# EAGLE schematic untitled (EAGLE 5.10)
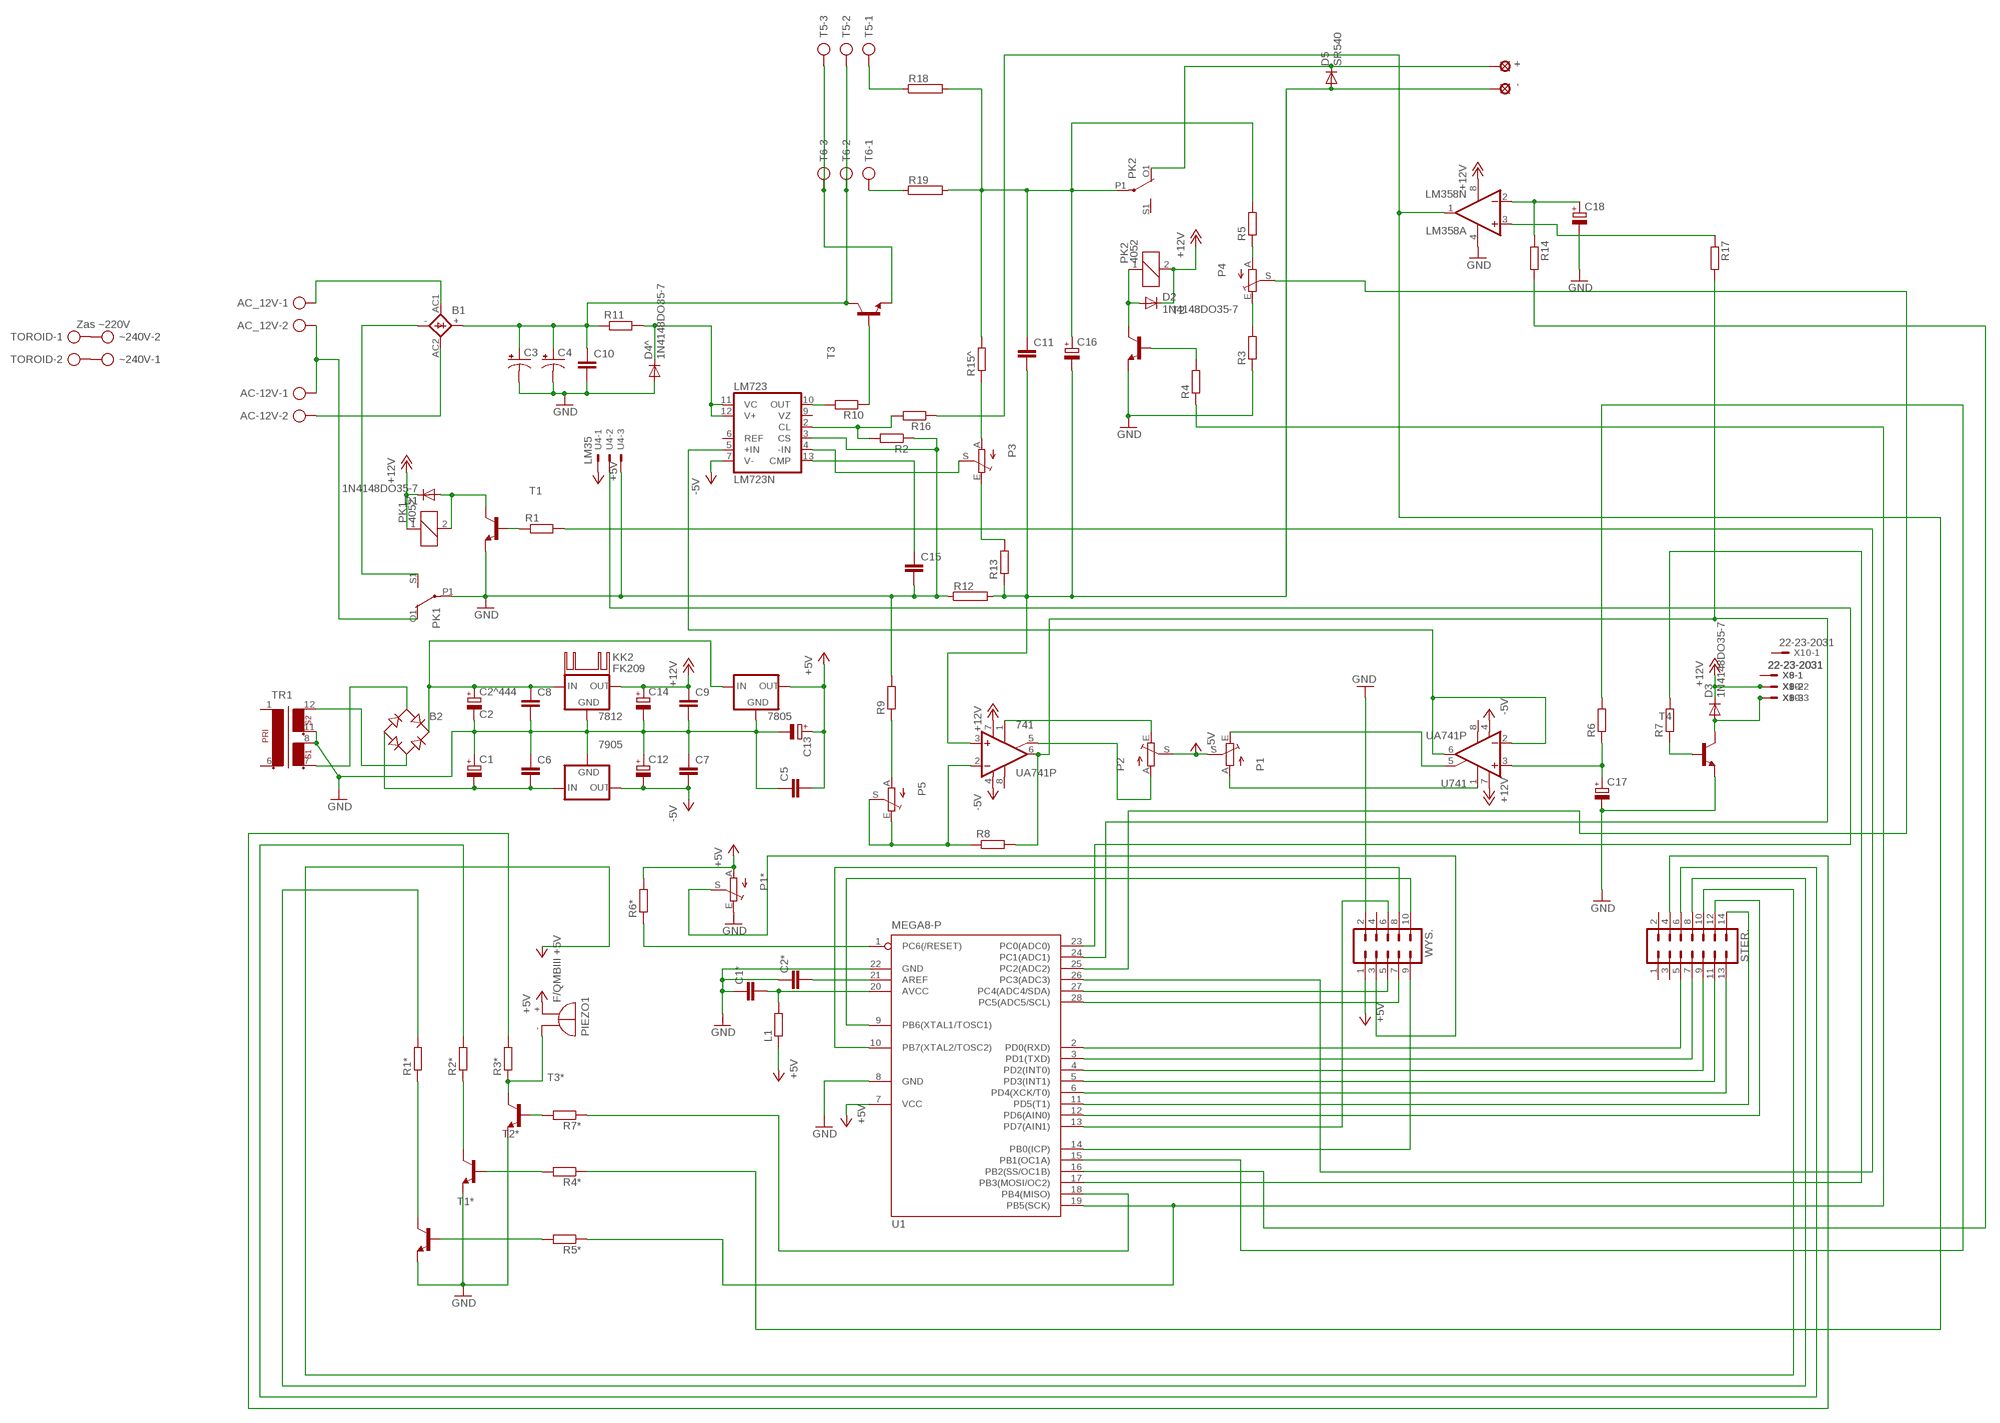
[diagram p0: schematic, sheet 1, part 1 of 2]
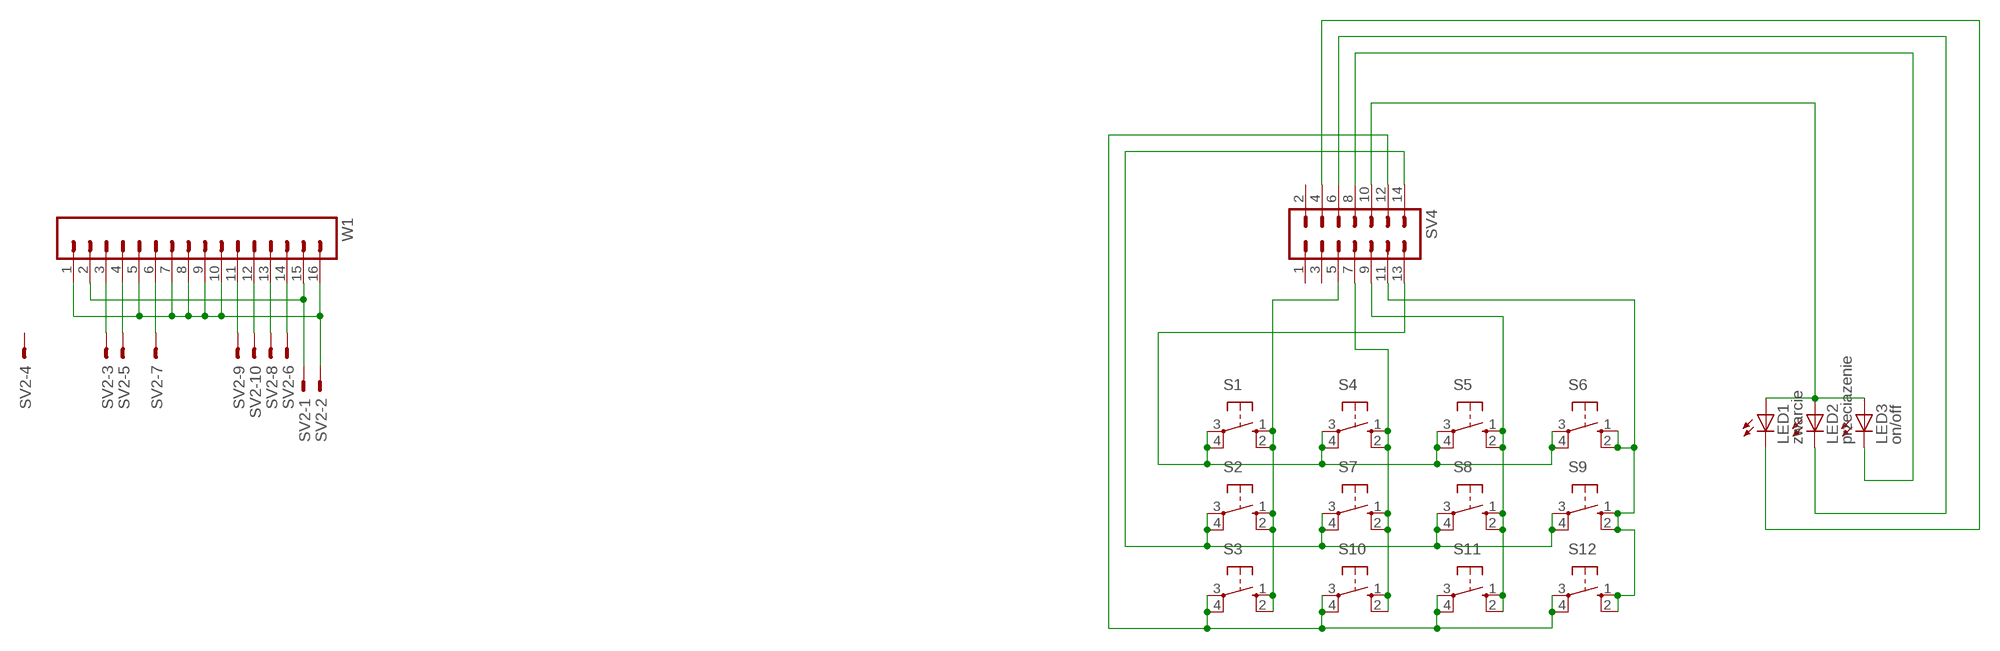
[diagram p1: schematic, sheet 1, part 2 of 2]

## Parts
741  UA741P  [DIL08]
7805  78XXS  [78XXS]
7812  78XXS  [78XXS]
7905  79XXS  [79XXS]
+  LSP10  [LSP10]
-  LSP10  [LSP10]
AC-12V  AK500/2  [AK500/2]
AC_12V  AK500/2  [AK500/2]
B1  FBM  [FBM]
B2  RB1A  [RB1A]
C1  CPOL-EUE3.5-10  [E3,5-10]
C1*  C-EU050-030X075  [C050-030X075]
C2*  C-EU050-030X075  [C050-030X075]
C2^444  C2  CPOL-EUE3.5-10  [E3,5-10]
C3  CPOL-USE7.5-18  [E7,5-18]
C4  CPOL-USE7.5-18  [E7,5-18]
C5  C-EU050-030X075  [C050-030X075]
C6  C-EU050-030X075  [C050-030X075]
C7  C-EU050-030X075  [C050-030X075]
C8  C-EU050-030X075  [C050-030X075]
C9  C-EU050-030X075  [C050-030X075]
C10  C-EU050-030X075  [C050-030X075]
C11  C-EU050-030X075  [C050-030X075]
C12  CPOL-EUE3.5-8  [E3,5-8]
C13  CPOL-EUE3.5-8  [E3,5-8]
C14  CPOL-EUE3.5-8  [E3,5-8]
C15  C-EU050-055X075  [C050-055X075]
C16  CPOL-EUE2.5-6  [E2,5-6]
C17  CPOL-EUE2.5-6  [E2,5-6]
C18  CPOL-EUE2.5-6  [E2,5-6]
D1  1N4148DO35-7  [DO35-7]
D2  1N4148DO35-7  [DO35-7]
D3  1N4148DO35-7  [DO35-7]
D4^  1N4148DO35-7  [DO35-7]
D5  SR540  BYT08P  [TO220ACS]
KK2  FK209  [FK209]
L1  R-EU_0204/7  [0204/7]
LED1  zwarcie  LEDSQR2X5  [LED2X5]
LED2  przeciazenie  LEDSQR2X5  [LED2X5]
LED3  on/off  LEDSQR2X5  [LED2X5]
LM358  LM358N  [DIL08]
LM723  LM723N  [DIL14]
P1  TRIM_EU-SP19L  [SP19L]
P1*  TRIM_EU-CA6V  [CA6V]
P2  TRIM_EU-SP19L  [SP19L]
P3  TRIM_EU-SP19L  [SP19L]
P4  TRIM_EU-SP19L  [SP19L]
P5  TRIM_EU-SP19L  [SP19L]
PIEZO1  F/QMBIII  [F/QMBIII]
PK1  4052  [F4052]
PK2  4052  [F4052]
R1  R-EU_0204/7  [0204/7]
R1*  R-EU_0204/7  [0204/7]
R2  R-EU_0204/7  [0204/7]
R2*  R-EU_0204/7  [0204/7]
R3  R-EU_0204/7  [0204/7]
R3*  R-EU_0204/7  [0204/7]
R4  R-EU_0204/7  [0204/7]
R4*  R-EU_0204/7  [0204/7]
R5  R-EU_0204/7  [0204/7]
R5*  R-EU_0204/7  [0204/7]
R6  R-EU_0204/7  [0204/7]
R6*  R-EU_0204/7  [0204/7]
R7  R-EU_0204/7  [0204/7]
R7*  R-EU_0204/7  [0204/7]
R8  R-EU_0204/7  [0204/7]
R9  R-EU_0204/7  [0204/7]
R10  R-EU_0204/7  [0204/7]
R11  R-EU_0204/7  [0204/7]
R12  RKH206-8  [KH206-8]
R13  R-EU_0204/7  [0204/7]
R14  R-EU_0204/7  [0204/7]
R15^  R-EU_0204/7  [0204/7]
R16  R-EU_0204/7  [0204/7]
R17  R-EU_0204/7  [0204/7]
R18  RKH206-8  [KH206-8]
R19  RKH206-8  [KH206-8]
S1  10-XX  [B3F-10XX]
S2  10-XX  [B3F-10XX]
S3  10-XX  [B3F-10XX]
S4  10-XX  [B3F-10XX]
S5  10-XX  [B3F-10XX]
S6  10-XX  [B3F-10XX]
S7  10-XX  [B3F-10XX]
S8  10-XX  [B3F-10XX]
S9  10-XX  [B3F-10XX]
S10  10-XX  [B3F-10XX]
S11  10-XX  [B3F-10XX]
S12  10-XX  [B3F-10XX]
STER.  ML14  [ML14]
SV2  ML10E  [ML10]
SV4  ML14  [ML14]
T1  BC337-16-NPN-TO92-EBC  [TO92-EBC]
T1*  BC337-16-NPN-TO92-EBC  [TO92-EBC]
T2  BC337-16-NPN-TO92-EBC  [TO92-EBC]
T2*  BC337-16-NPN-TO92-EBC  [TO92-EBC]
T3  -NPN-TO126V  [TO126V]
T3*  BC337-16-NPN-TO92-EBC  [TO92-EBC]
T4  -NPN-TO126V  [TO126V]
T5  AK500/3  [AK500/3]
T6  AK500/3  [AK500/3]
TOROID  AK500/2  [AK500/2]
TR1  EI48-2  [EI48-2]
U1  MEGA8-P  [DIL28-3]
U4  LM35  22-23-2031  [22-23-2031]
U741  UA741P  [DIL08]
W1  M16  [16P]
WYS.  ML10  [ML10]
X8  22-23-2031  [22-23-2031]
X9  22-23-2031  [22-23-2031]
X10  22-23-2031  [22-23-2031]
~240V  Zas ~220V  AK500/2  [AK500/2]

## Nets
+5V: 7805.OUT C5.2 C13.+ L1.1 P1*.A PIEZO1.+(-) R6*.2 STER..10 U1.7(VCC) U4.1 WYS..1
+12V: 741.7(V+) 7812.OUT C9.1 C14.+ D1.C D2.C D3.C LM358.8(P:V+) PK1.1 PK2.2 U741.7(V+) X8.2 X9.2 X10.2
-5V: 741.4(V-) 7905.OUT C7.2 C12.- LM723.7(V-) P1.S P2.S U741.4(V-)
D5: +.MP D5.C PK2.O1(2:O)
E1: T3.1(E) T5.3 T6.3
GND: 7805.GND 7812.GND 7905.GND C1*.1 C1.+ C2*.1 C2^444.- C3.- C4.- C5.1 C6.1 C7.1 C8.2 C9.2 C10.2 C12.+ C13.- C14.- C15.2 C17.- C18.- D4^.A LM358.4(P:V-) LM723.3(CS) P1*.E PK1.P1(2:P) R2.1 R3.1 R9.2 R12.1 T1*.E T1.E T2*.E T2.E T3*.E T4.1(E) TR1.8 TR1.11 U1.8(GND) U1.22(GND) U4.3 WYS..2
N$3: C1*.2 L1.2 U1.20(AVCC)
N$9: AC-12V.1 AC_12V.2 PK1.O1(2:O)
N$10: B1.- PK1.S1(2:S)
N$11: LM723.10(OUT) R10.2
N$12: TOROID.2 ~240V.1
N$13: TOROID.1 ~240V.2
N$14: R10.1 T3.3(B)
N$15: D1.A PK1.2 T1.C
N$16: SV2.1 W1.2 W1.15
N$20: AC_12V.1 B1.AC1
N$21: AC-12V.2 B1.AC2
N$22: R1.1 T1.B
N$23: R18.1 T5.1
N$25: D4^.C LM723.11(VC) LM723.12(V+) R11.2
N$26: R1.2 U1.26(PC3(ADC3))
N$27: C2*.2 U1.21(AREF)
N$28: R19.1 T6.1
N$30: 741.3(+IN) -.MP C11.2 C16.- D5.A R12.2 R13.1
N$32: R4.2 T2.B
N$33: D2.A PK2.1 T2.C
N$34: C11.1 C16.+ PK2.P1(2:P) R5.2 R15^.2 R18.2 R19.2
N$35: B2.AC1 TR1.7
N$36: R7.2 U1.17(PB3(MOSI/OC2))
N$38: B2.AC2 TR1.12
N$54: 7805.IN 7812.IN B2.+ C2^444.+ C8.1
N$62: 7905.IN B2.- C1.- C6.2
N$76: C15.1 LM723.13(CMP)
N$77: 741.5(ON2) P2.A
N$78: P5.A R9.1
N$79: 741.2(-IN) P5.E P5.S R8.1
N$80: 741.6(OUT) R8.2 R17.2 U1.24(PC1(ADC1))
N$81: LM723.2(CL) R2.2 R16.2
N$82: 741.1(ON1) P2.E
N$87: P1.E U741.5(ON2)
N$88: P1.A U741.1(ON1)
N$89: LM723.5(+IN) U741.2(-IN) U741.6(OUT)
N$91: C17.+ R6.1 U741.3(+IN)
N$92: STER..5 U1.2(PD0(RXD))
N$99: X8.1 X9.1
N$100: R7.1 T4.3(B)
N$101: STER..7 U1.3(PD1(TXD))
N$102: D3.A T4.2(C) X8.3 X9.3 X10.3
N$105: U1.23(PC0(ADC0)) U4.2
N$108: P4.A R5.1
N$109: P4.E R3.2
N$111: STER..9 U1.4(PD2(INT0))
N$119: STER..11 U1.5(PD3(INT1))
N$120: C18.+ LM358.2(A:-IN) R14.1
N$121: LM358.3(A:+IN) R17.1
N$122: STER..13 U1.6(PD4(XCK/T0))
N$123: LM358.1(A:OUT) R4*.1 R16.1
N$141: P3.E R13.2
N$142: P3.A R15^.1
N$143: LM723.4(-IN) P3.S
N$150: STER..14 U1.11(PD5(T1))
N$157: STER..12 U1.12(PD6(AIN0))
N$161: PIEZO1.-(+) R3*.1 T3*.C
N$162: R4*.2 T2*.B
N$176: R7*.2 T3*.B
N$179: R5*.2 T1*.B
N$180: R2*.1 T2*.C
N$182: R1*.1 T1*.C
N$183: R3*.2 STER..4
N$185: R7*.1 U1.18(PB4(MISO))
N$186: R4.1 R5*.1 U1.19(PB5(SCK))
N$187: P1*.S WYS..3
N$188: R1*.2 STER..8
N$190: U1.13(PD7(AIN1)) WYS..6
N$192: R6*.1 U1.1(PC6(/RESET))
N$193: U1.27(PC4(ADC4/SDA)) WYS..5
N$194: U1.9(PB6(XTAL1/TOSC1)) WYS..10
N$195: U1.10(PB7(XTAL2/TOSC2)) WYS..8
N$196: U1.28(PC5(ADC5/SCL)) WYS..7
N$197: U1.14(PB0(ICP)) WYS..9
N$259: SV2.3 W1.3
N$260: SV2.5 W1.4
N$261: SV2.7 W1.6
N$262: SV2.9 W1.11
N$263: SV2.10 W1.12
N$264: SV2.8 W1.13
N$265: SV2.6 W1.14
N$278: S6.1(S) S6.2(S1) S9.1(S) S9.2(S1) S12.1(S) S12.2(S1) SV4.11
N$280: S3.3(P) S3.4(P1) S10.3(P) S10.4(P1) S11.3(P) S11.4(P1) S12.3(P) S12.4(P1) SV4.12
N$282: S2.3(P) S2.4(P1) S7.3(P) S7.4(P1) S8.3(P) S8.4(P1) S9.3(P) S9.4(P1) SV4.14
N$283: S1.3(P) S1.4(P1) S4.3(P) S4.4(P1) S5.3(P) S5.4(P1) S6.3(P) S6.4(P1) SV4.13
N$284: S5.1(S) S5.2(S1) S8.1(S) S8.2(S1) S11.1(S) S11.2(S1) SV4.9
N$286: SV2.2 W1.1 W1.5 W1.7 W1.8 W1.9 W1.10 W1.16
N$287: S4.1(S) S4.2(S1) S7.1(S) S7.2(S1) S10.1(S) S10.2(S1) SV4.7
N$289: S1.1(S) S1.2(S1) S2.1(S) S2.2(S1) S3.1(S) S3.2(S1) SV4.5
N$311: LED1.A LED2.A LED3.A SV4.10
N$312: LED3.K(C) SV4.8
N$354: P4.S U1.25(PC2(ADC2))
N$357: R6.2 U1.15(PB1(OC1A))
N$358: R14.2 U1.16(PB2(SS/OC1B))
N$362: R2*.2 STER..6
N$375: LED2.K(C) SV4.6
N$376: LED1.K(C) SV4.4
T6: B1.+ C3.+ C4.+ C10.1 R11.1 T3.2(C) T5.2 T6.2
Unconnected: 741.8(OPT) LM358.5(B:+IN) LM358.6(B:-IN) LM358.7(B:OUT) LM723.6(REF) LM723.9(VZ) PK1.O2(3:O) PK1.P2(3:P) PK1.S2(3:S) PK2.O2(3:O) PK2.P2(3:P) PK2.S1(2:S) PK2.S2(3:S) STER..1 STER..2 STER..3 SV2.4 SV4.1 SV4.2 SV4.3 TR1.1 TR1.6 U741.8(OPT) WYS..4 X10.1

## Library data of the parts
741 U741 = linear:*741: OP AMP
7805 7812 = v-reg:78XXS: VOLTAGE REGULATOR
7905 = v-reg:79XXS: VOLTAGE REGULATOR
+ - = solpad:LSP10: SOLDER PAD
AC-12V AC_12V TOROID ~240V = con-ptr500:AK500/2: CONNECTOR
B1 = rectifier:FBM: GENERAL INSTRUMENT RECTIFIER
B2 = rectifier:RB1A: RECTIFIER 1 A
C1 C2^444 C12-C14 C16-C18 = rcl:CPOL-EU: POLARIZED CAPACITOR, European symbol
C1* C2* C5-C11 C15 = rcl:C-EU: CAPACITOR, European symbol
C3 C4 = rcl:CPOL-US: POLARIZED CAPACITOR, American symbol
D1-D3 D4^ = diode:1N4148: DIODE
D5 = diode:BYT08P: DIODE
KK2 = Radiatory:FK209: HEATSINK
L1 R1 R1* R2 R2* R3 R3* R4 R4* R5 R5* R6 R6* R7 R7* R8-R11 R13 R14 R15^ R16 R17 = rcl:R-EU_: RESISTOR, European symbol
LED1-LED3 = led:LED: LED
LM358 = linear:LM358: OP AMP also LM158; LM258; LM2904 Source: http://cache.national.com/ds/LM/LM158.pdf
LM723 = linear:*723: Positive VOLTAGE REGULATOR
P1 P1* P2-P5 = pot:TRIM_EU-: POTENTIOMETER
PIEZO1 = buzzer:F/QMBIII: BUZZER
PK1 PK2 = relay:4052: RELAY 2 x switch, Finder
R12 R18 R19 = resistor-power:R: Power Resitor
S1-S12 = switch-omron:10-XX: OMRON SWITCH
STER. SV4 = con-ml:ML14: HARTING
SV2 = con-ml:ML10E: HARTING
T1 T1* T2 T2* T3 T3* T4 = transistor:*-NPN-: NPN Transistror BF959 corrected 2008.03.06
T5 T6 = con-ptr500:AK500/3: CONNECTOR
TR1 = trafo:EI48-2: TRANSFORMER 1 primary winding, 2 secondary windings ERA
U1 = atmel:MEGA8-P: MICROCONTROLLER 8 Kbytes FLASH, 1 kbytes SRAM, 512 bytes EEPROM, USART, 4-channel 10 bit ADC, 2-channel 8 bit ADC Pin compatible with Atmega48, ATMega88, ATMega168 Source: avr.lbr
U4 X8-X10 = con-molex:22-23-2031: .100" (2.54mm) Center Header - 3 Pin
W1 = con-amp-quick:M16: AMP QUICK CONNECTOR
WYS. = con-ml:ML10: HARTING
